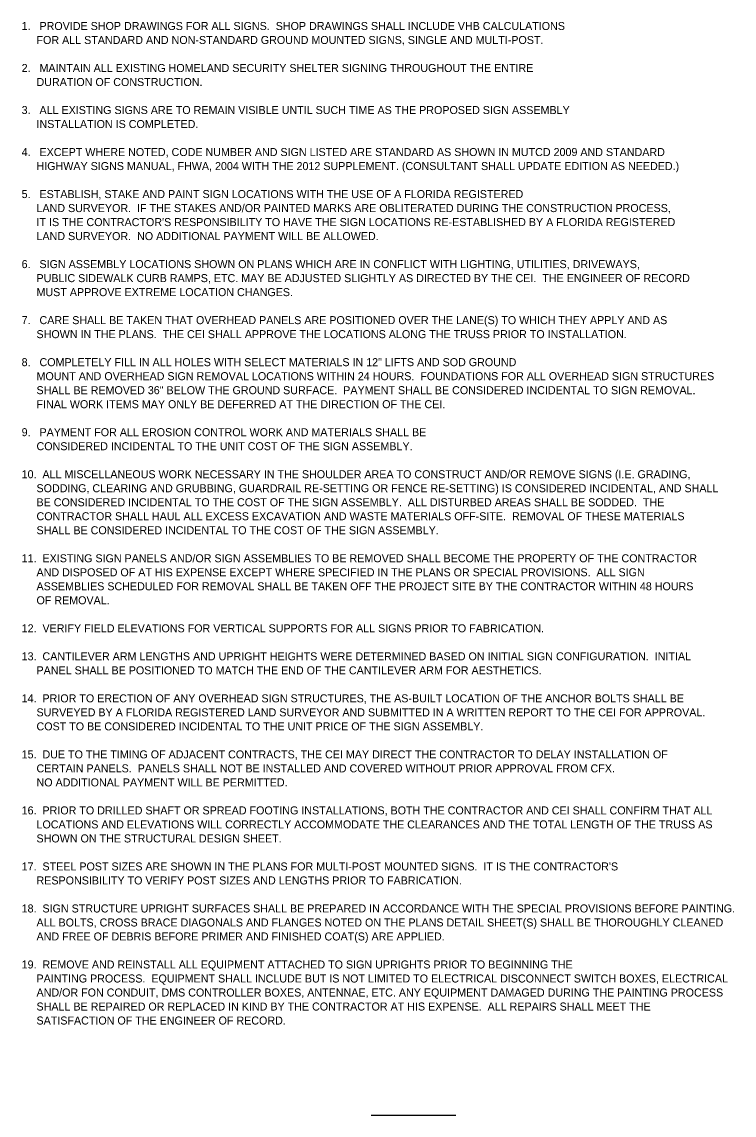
# Model space of a CAD drawing. Extents: x 2479946 to 2483081, y 3677527 to 3681234.
# Drawn here: x 2481723 to 2482323, y 3680275 to 3681197 of the extents above; entities that cross this region are included whole.
import ezdxf

# ---------------------------------------------------------------- set-up
doc = ezdxf.new("R2010")
doc.units = 0
doc.layers.add('40', color=7, linetype='Continuous')

msp = doc.modelspace()

# ---------------------------------------------------------------- linework, layer by layer
at = {"layer": '40'}
msp.add_line((2482017.18, 3680274.73), (2482088.3, 3680274.73), dxfattribs=at)

# ---------------------------------------------------------------- texts
for s, p in [('1.   PROVIDE SHOP DRAWINGS FOR ALL SIGNS.  SHOP DRAWINGS SHALL INCLUDE VHB CALCULATIONS ', (2481722.45, 3681189.83)), ('     FOR ALL STANDARD AND NON-STANDARD GROUND MOUNTED SIGNS, SINGLE AND MULTI-POST.', (2481722.45, 3681178.02)), ('2.   MAINTAIN ALL EXISTING HOMELAND SECURITY SHELTER SIGNING THROUGHOUT THE ENTIRE ', (2481722.45, 3681154.39)), ('     DURATION OF CONSTRUCTION.', (2481722.45, 3681142.58)), ('3.   ALL EXISTING SIGNS ARE TO REMAIN VISIBLE UNTIL SUCH TIME AS THE PROPOSED SIGN ASSEMBLY ', (2481722.45, 3681118.95)), ('     INSTALLATION IS COMPLETED.', (2481722.45, 3681107.14)), ('4.   EXCEPT WHERE NOTED, CODE NUMBER AND SIGN LISTED ARE STANDARD AS SHOWN IN MUTCD 2009 AND STANDARD ', (2481722.45, 3681083.52)), ('     HIGHWAY SIGNS MANUAL, FHWA, 2004 WITH THE 2012 SUPPLEMENT. (CONSULTANT SHALL UPDATE EDITION AS NEEDED.)', (2481722.45, 3681071.7)), ('5.   ESTABLISH, STAKE AND PAINT SIGN LOCATIONS WITH THE USE OF A FLORIDA REGISTERED ', (2481722.45, 3681048.08)), ('     LAND SURVEYOR.  IF THE STAKES AND/OR PAINTED MARKS ARE OBLITERATED DURING THE CONSTRUCTION PROCESS, ', (2481722.45, 3681036.27)), ("     IT IS THE CONTRACTOR'S RESPONSIBILITY TO HAVE THE SIGN LOCATIONS RE-ESTABLISHED BY A FLORIDA REGISTERED ", (2481722.45, 3681024.45)), ('     LAND SURVEYOR.  NO ADDITIONAL PAYMENT WILL BE ALLOWED.', (2481722.45, 3681012.64)), ('6.   SIGN ASSEMBLY LOCATIONS SHOWN ON PLANS WHICH ARE IN CONFLICT WITH LIGHTING, UTILITIES, DRIVEWAYS, ', (2481722.45, 3680989.02)), ('     PUBLIC SIDEWALK CURB RAMPS, ETC. MAY BE ADJUSTED SLIGHTLY AS DIRECTED BY THE CEI.  THE ENGINEER OF RECORD', (2481722.45, 3680977.2)), ('     MUST APPROVE EXTREME LOCATION CHANGES. ', (2481722.45, 3680965.39)), ('7.   CARE SHALL BE TAKEN THAT OVERHEAD PANELS ARE POSITIONED OVER THE LANE(S) TO WHICH THEY APPLY AND AS ', (2481722.45, 3680941.77)), ('     SHOWN IN THE PLANS.  THE CEI SHALL APPROVE THE LOCATIONS ALONG THE TRUSS PRIOR TO INSTALLATION.', (2481722.45, 3680929.95)), ('8.   COMPLETELY FILL IN ALL HOLES WITH SELECT MATERIALS IN 12" LIFTS AND SOD GROUND ', (2481722.45, 3680906.33)), ('     MOUNT AND OVERHEAD SIGN REMOVAL LOCATIONS WITHIN 24 HOURS.  FOUNDATIONS FOR ALL OVERHEAD SIGN STRUCTURES ', (2481722.45, 3680894.52)), ('     SHALL BE REMOVED 36" BELOW THE GROUND SURFACE.  PAYMENT SHALL BE CONSIDERED INCIDENTAL TO SIGN REMOVAL.', (2481722.45, 3680882.7)), ('     FINAL WORK ITEMS MAY ONLY BE DEFERRED AT THE DIRECTION OF THE CEI.', (2481722.45, 3680870.89)), ('9.   PAYMENT FOR ALL EROSION CONTROL WORK AND MATERIALS SHALL BE', (2481722.45, 3680847.27)), ('     CONSIDERED INCIDENTAL TO THE UNIT COST OF THE SIGN ASSEMBLY.', (2481722.45, 3680835.45)), ('10.  ALL MISCELLANEOUS WORK NECESSARY IN THE SHOULDER AREA TO CONSTRUCT AND/OR REMOVE SIGNS (I.E. GRADING, ', (2481722.45, 3680811.83)), ('     SODDING, CLEARING AND GRUBBING, GUARDRAIL RE-SETTING OR FENCE RE-SETTING) IS CONSIDERED INCIDENTAL, AND SHALL ', (2481722.45, 3680800.02)), ('     BE CONSIDERED INCIDENTAL TO THE COST OF THE SIGN ASSEMBLY.  ALL DISTURBED AREAS SHALL BE SODDED.  THE  ', (2481722.45, 3680788.2)), ('     CONTRACTOR SHALL HAUL ALL EXCESS EXCAVATION AND WASTE MATERIALS OFF-SITE.  REMOVAL OF THESE MATERIALS  ', (2481722.45, 3680776.39)), ('     SHALL BE CONSIDERED INCIDENTAL TO THE COST OF THE SIGN ASSEMBLY.', (2481722.45, 3680764.58)), ('11.  EXISTING SIGN PANELS AND/OR SIGN ASSEMBLIES TO BE REMOVED SHALL BECOME THE PROPERTY OF THE CONTRACTOR ', (2481722.45, 3680740.95)), ('     AND DISPOSED OF AT HIS EXPENSE EXCEPT WHERE SPECIFIED IN THE PLANS OR SPECIAL PROVISIONS.  ALL SIGN ', (2481722.45, 3680729.14)), ('     ASSEMBLIES SCHEDULED FOR REMOVAL SHALL BE TAKEN OFF THE PROJECT SITE BY THE CONTRACTOR WITHIN 48 HOURS ', (2481722.45, 3680717.33)), ('     OF REMOVAL.', (2481722.45, 3680705.52)), ('12.  VERIFY FIELD ELEVATIONS FOR VERTICAL SUPPORTS FOR ALL SIGNS PRIOR TO FABRICATION.', (2481722.45, 3680681.89)), ('13.  CANTILEVER ARM LENGTHS AND UPRIGHT HEIGHTS WERE DETERMINED BASED ON INITIAL SIGN CONFIGURATION.  INITIAL', (2481722.45, 3680658.27)), ('     PANEL SHALL BE POSITIONED TO MATCH THE END OF THE CANTILEVER ARM FOR AESTHETICS.', (2481722.45, 3680646.45)), ('14.  PRIOR TO ERECTION OF ANY OVERHEAD SIGN STRUCTURES, THE AS-BUILT LOCATION OF THE ANCHOR BOLTS SHALL BE ', (2481722.45, 3680622.83)), ('     SURVEYED BY A FLORIDA REGISTERED LAND SURVEYOR AND SUBMITTED IN A WRITTEN REPORT TO THE CEI FOR APPROVAL.  ', (2481722.45, 3680611.02)), ('     COST TO BE CONSIDERED INCIDENTAL TO THE UNIT PRICE OF THE SIGN ASSEMBLY.', (2481722.45, 3680599.2)), ('15.  DUE TO THE TIMING OF ADJACENT CONTRACTS, THE CEI MAY DIRECT THE CONTRACTOR TO DELAY INSTALLATION OF', (2481722.45, 3680575.58)), ('     CERTAIN PANELS.  PANELS SHALL NOT BE INSTALLED AND COVERED WITHOUT PRIOR APPROVAL FROM CFX.', (2481722.45, 3680563.77)), ('     NO ADDITIONAL PAYMENT WILL BE PERMITTED.', (2481722.45, 3680551.95)), ('16.  PRIOR TO DRILLED SHAFT OR SPREAD FOOTING INSTALLATIONS, BOTH THE CONTRACTOR AND CEI SHALL CONFIRM THAT ALL', (2481722.45, 3680528.33)), ('     LOCATIONS AND ELEVATIONS WILL CORRECTLY ACCOMMODATE THE CLEARANCES AND THE TOTAL LENGTH OF THE TRUSS AS', (2481722.45, 3680516.52)), ('     SHOWN ON THE STRUCTURAL DESIGN SHEET.', (2481722.45, 3680504.7)), ("17.  STEEL POST SIZES ARE SHOWN IN THE PLANS FOR MULTI-POST MOUNTED SIGNS.  IT IS THE CONTRACTOR'S ", (2481722.45, 3680481.08)), ('     RESPONSIBILITY TO VERIFY POST SIZES AND LENGTHS PRIOR TO FABRICATION.', (2481722.45, 3680469.27)), ('18.  SIGN STRUCTURE UPRIGHT SURFACES SHALL BE PREPARED IN ACCORDANCE WITH THE SPECIAL PROVISIONS BEFORE PAINTING.', (2481722.45, 3680445.64)), ('     ALL BOLTS, CROSS BRACE DIAGONALS AND FLANGES NOTED ON THE PLANS DETAIL SHEET(S) SHALL BE THOROUGHLY CLEANED', (2481722.45, 3680433.83)), ('     AND FREE OF DEBRIS BEFORE PRIMER AND FINISHED COAT(S) ARE APPLIED.', (2481722.45, 3680422.02)), ('19.  REMOVE AND REINSTALL ALL EQUIPMENT ATTACHED TO SIGN UPRIGHTS PRIOR TO BEGINNING THE', (2481722.45, 3680398.39)), ('     PAINTING PROCESS.  EQUIPMENT SHALL INCLUDE BUT IS NOT LIMITED TO ELECTRICAL DISCONNECT SWITCH BOXES, ELECTRICAL', (2481722.45, 3680386.58)), ('     AND/OR FON CONDUIT, DMS CONTROLLER BOXES, ANTENNAE, ETC. ANY EQUIPMENT DAMAGED DURING THE PAINTING PROCESS ', (2481722.45, 3680374.77)), ('     SHALL BE REPAIRED OR REPLACED IN KIND BY THE CONTRACTOR AT HIS EXPENSE.  ALL REPAIRS SHALL MEET THE ', (2481722.45, 3680362.95)), ('     SATISFACTION OF THE ENGINEER OF RECORD.', (2481722.45, 3680351.14))]:
    msp.add_text(s, height=6.75, dxfattribs=at).set_placement(p)

doc.saveas('drawing.dxf')
